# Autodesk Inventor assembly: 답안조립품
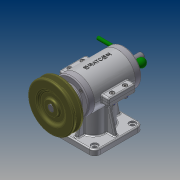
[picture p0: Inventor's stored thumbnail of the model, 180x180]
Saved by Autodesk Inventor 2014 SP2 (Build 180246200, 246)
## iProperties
Created: 2015-12
Part Number: 답안조립품
Document SubType Name: Assembly
Designer: Administrator
Author: Administrator
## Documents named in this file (19)
- C:\Users\Administrator\Desktop\351207V1006\답안조립품.iam
- C:\Users\Administrator\Desktop\351207V1006\본체.ipt
- C:\Users\Administrator\Desktop\351207V1006\V-벨트풀리.ipt
- C:\Users\Administrator\Desktop\351207V1006\너트 M4.ipt
- C:\Users\Administrator\Desktop\351207V1006\뒤커버.ipt
- C:\Users\Administrator\Desktop\351207V1006\레바.ipt
- C:\Users\Administrator\Desktop\351207V1006\멈춤나사 M3x8.ipt
- C:\Users\Administrator\Desktop\351207V1006\베어링 6201.ipt
- C:\Users\Administrator\Desktop\351207V1006\베어링 6202.ipt
- C:\Users\Administrator\Desktop\351207V1006\본체커버.ipt
- C:\Users\Administrator\Desktop\351207V1006\볼트 M3x0.5x8.ipt
- C:\Users\Administrator\Desktop\351207V1006\볼트 M4 x 16.ipt
- C:\Users\Administrator\Desktop\351207V1006\스프링.ipt
- C:\Users\Administrator\Desktop\351207V1006\슬라이드.ipt
- C:\Users\Administrator\Desktop\351207V1006\앞커버.ipt
- C:\Users\Administrator\Desktop\351207V1006\오일실 12 22 7.ipt
- C:\Users\Administrator\Desktop\351207V1006\와셔 ST 4-100.ipt
- C:\Users\Administrator\Desktop\351207V1006\키 4 x 4 x 18.ipt
- C:\Users\Administrator\Desktop\351207V1006\편심축.ipt
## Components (13 placed, 4 different names)
1. V-벨트풀리:1 — 각도:2
2. ISO 4762 M4 x 16:1
3. ISO 4032 M4:1
4. ISO 7091 ST 4 - 100 HV:1
5. ISO 4762 M4 x 16:2
6. ISO 4032 M4:2
7. ISO 7091 ST 4 - 100 HV:2
8. ISO 4762 M4 x 16:3
9. ISO 4032 M4:3
10. ISO 7091 ST 4 - 100 HV:3
11. ISO 4762 M4 x 16:4
12. ISO 4032 M4:4
13. ISO 7091 ST 4 - 100 HV:4
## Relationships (1: Angle 1)
- 각도:2 [Angle]: V-벨트풀리:1
